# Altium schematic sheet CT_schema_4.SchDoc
size 205 x 258 mm
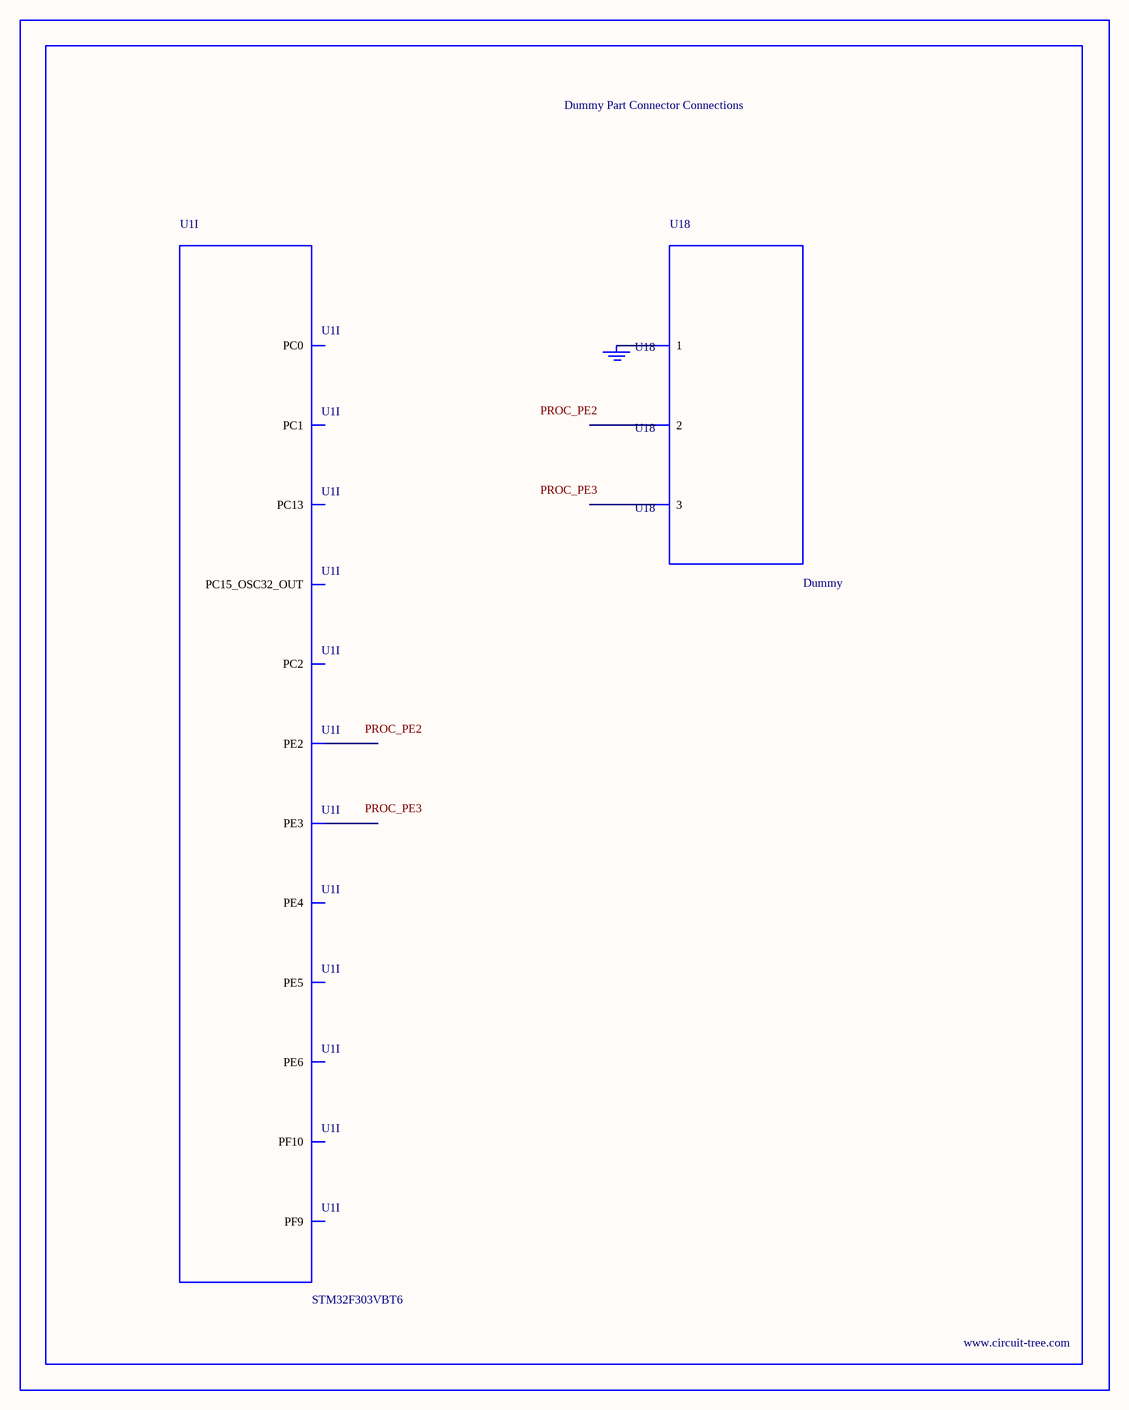
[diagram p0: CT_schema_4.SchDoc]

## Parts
BORDER3  (no value)
GND_INSTANCE_3_0  (no value)
U1  STM32F303VBT6  [LQFP100]  (part I of 9)
U18  Dummy  [DUMMY_PACKAGE_164]

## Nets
NetGND_INSTANCE_3_0_0: GND_INSTANCE_3_0.0(GND) U18.1

Not connected (* = marked no-connect by the designer): U1 1(PE2) 2(PE3) 3(PE4) 4(PE5) 5(PE6) 7(PC13) 9(PC15_OSC32_OUT) 10(PF9) 11(PF10) 15(PC0) 16(PC1) 17(PC2); U18 2 3

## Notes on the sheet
- Labels drawn without touching a wire or pin: PROC_PE2, PROC_PE3

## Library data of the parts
BORDER3 = BORDER_PAGE3
GND_INSTANCE_3_0 = GND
